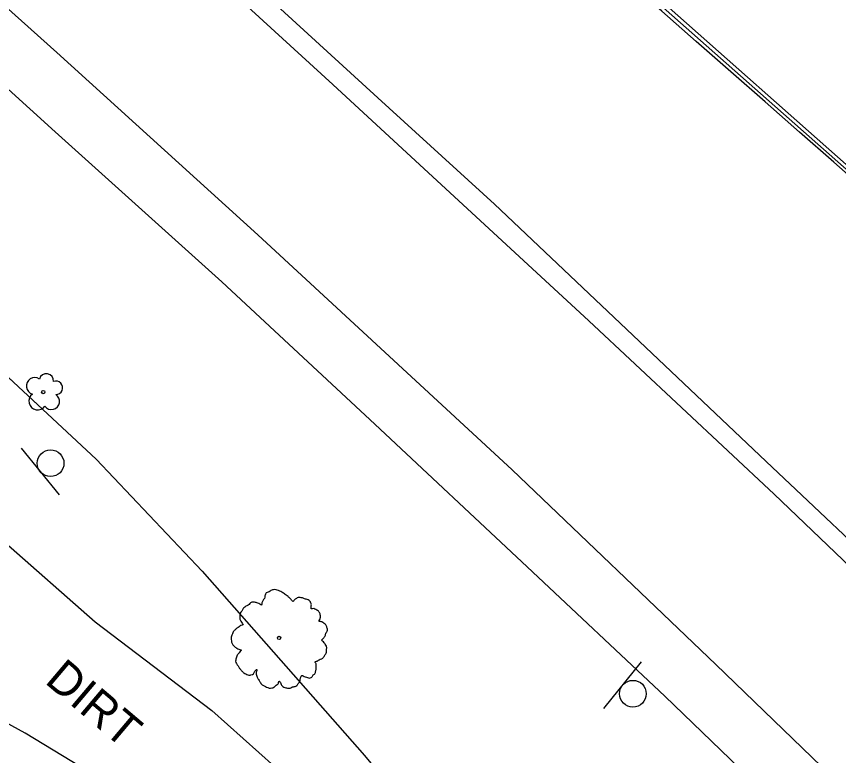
# Model space of a CAD drawing. Extents: x 2076109 to 2080761, y 592812 to 596750.
# Drawn here: x 2077395.6 to 2077518.8, y 595507.7 to 595618.3 of the extents above; entities that cross this region are included whole.
import ezdxf

# ---------------------------------------------------------------- set-up
doc = ezdxf.new("R2010")
doc.units = 0
for name, color, linetype in [('Default', 7, 'Continuous'), ('RD_EX_BldgApp', 7, 'Continuous'), ('RD_EX_Fence_ChLk', 7, 'Continuous'), ('RD_EX_Misc', 7, 'Continuous'), ('RD_EX_Road', 7, 'Continuous'), ('RD_EX_Road_txCode', 7, 'Continuous'), ('RD_EX_VEG', 7, 'Continuous'), ('RD_HC_Cl', 7, 'Continuous')]:
    doc.layers.add(name, color=color, linetype=linetype)

msp = doc.modelspace()

# ---------------------------------------------------------------- linework, layer by layer
at = {"layer": 'Default'}
for p, q in [((2077364.31, 595733.06), (2078453.96, 594769.07)), ((2077364.31, 595733.06), (2078453.96, 594769.07)), ((2077404.89, 595698.18), (2078420.27, 594797.03)), ((2077404.89, 595698.18), (2078420.27, 594797.03))]:
    msp.add_line(p, q, dxfattribs=at)
msp.add_arc((2035586.7, 547847.96), 63546.51, 48.5011873, 49.2923126, dxfattribs=at)
msp.add_arc((2035586.7, 547847.96), 63546.51, 48.5011873, 49.2923126, dxfattribs=at)
at = {"layer": 'RD_EX_BldgApp'}
for p, q in [((2077396.33, 595553.65), (2077402.01, 595546.67)), ((2077396.33, 595553.65), (2077402.01, 595546.67)), ((2077489.21, 595521.7), (2077483.57, 595514.69)), ((2077489.21, 595521.7), (2077483.57, 595514.69))]:
    msp.add_line(p, q, dxfattribs=at)
for centre in [(2077400.75, 595551.42), (2077400.75, 595551.42), (2077487.96, 595516.91), (2077487.96, 595516.91)]:
    msp.add_circle(centre, 2, dxfattribs=at)
at = {"layer": 'RD_EX_Fence_ChLk'}
msp.add_lwpolyline([(2077335.75, 595618.26), (2077356.53, 595599.53), (2077407.57, 595552.05), (2077423.46, 595535.25), (2077447.78, 595507.68), (2077494.27, 595451.57), (2077527.1, 595411.56), (2077548.1, 595385.61), (2077582.49, 595344.46)], dxfattribs=at)
msp.add_lwpolyline([(2077335.75, 595618.26), (2077356.53, 595599.53), (2077407.57, 595552.05), (2077423.46, 595535.25), (2077447.78, 595507.68), (2077494.27, 595451.57), (2077527.1, 595411.56), (2077548.1, 595385.61), (2077582.49, 595344.46)], dxfattribs=at)
at = {"layer": 'RD_EX_Misc'}
for points in [[(2077850.7, 595201.63), (2077820.53, 595232.8), (2077790.22, 595263.88), (2077762.8, 595291.76), (2077736.42, 595318.96), (2077709.92, 595346.36), (2077678.72, 595378.46), (2077649.91, 595408.22), (2077612.46, 595446.3), (2077577.19, 595481.07), (2077550.3, 595507.41), (2077509.12, 595546.77), (2077481.37, 595572.73), (2077443, 595608.1), (2077400.67, 595646.86), (2077373.88, 595670.82), (2077334.03, 595706.37), (2077304.56, 595732)], [(2077850.7, 595201.63), (2077820.53, 595232.8), (2077790.22, 595263.88), (2077762.8, 595291.76), (2077736.42, 595318.96), (2077709.92, 595346.36), (2077678.72, 595378.46), (2077649.91, 595408.22), (2077612.46, 595446.3), (2077577.19, 595481.07), (2077550.3, 595507.41), (2077509.12, 595546.77), (2077481.37, 595572.73), (2077443, 595608.1), (2077400.67, 595646.86), (2077373.88, 595670.82), (2077334.03, 595706.37), (2077304.56, 595732)], [(2077812.69, 595205.74), (2077779.15, 595240.73), (2077743.86, 595277.34), (2077707.16, 595314.93), (2077677.78, 595345.17), (2077641.95, 595381.51), (2077607.57, 595416.21), (2077570.67, 595452.82), (2077540.71, 595482.36), (2077500.4, 595521.29), (2077469.88, 595550.44), (2077431.8, 595585.6), (2077401.7, 595612.91), (2077373.73, 595637.96), (2077342.22, 595666.06), (2077323.28, 595683.05), (2077307.69, 595696.83), (2077294.47, 595708.58)], [(2077812.69, 595205.74), (2077779.15, 595240.73), (2077743.86, 595277.34), (2077707.16, 595314.93), (2077677.78, 595345.17), (2077641.95, 595381.51), (2077607.57, 595416.21), (2077570.67, 595452.82), (2077540.71, 595482.36), (2077500.4, 595521.29), (2077469.88, 595550.44), (2077431.8, 595585.6), (2077401.7, 595612.91), (2077373.73, 595637.96), (2077342.22, 595666.06), (2077323.28, 595683.05), (2077307.69, 595696.83), (2077294.47, 595708.58)]]:
    msp.add_lwpolyline(points, dxfattribs=at)
at = {"layer": 'RD_EX_Road'}
for points in [[(2077528.44, 595532.32), (2077507.93, 595551.7), (2077491.72, 595567.02), (2077467.24, 595590.18), (2077449.74, 595606.14), (2077431.68, 595622.71), (2077417.63, 595635.43), (2077400.96, 595650.59), (2077383.92, 595665.65), (2077365.24, 595682.19), (2077343.44, 595701.66), (2077326.52, 595716.21), (2077315.27, 595726.7), (2077317.91, 595731.12), (2077318.69, 595732.86), (2077319.09, 595734.63), (2077318.89, 595736.63), (2077318.61, 595737.93), (2077317.61, 595740.01), (2077315.19, 595742.84)], [(2077528.44, 595532.32), (2077507.93, 595551.7), (2077491.72, 595567.02), (2077467.24, 595590.18), (2077449.74, 595606.14), (2077431.68, 595622.71), (2077417.63, 595635.43), (2077400.96, 595650.59), (2077383.92, 595665.65), (2077365.24, 595682.19), (2077343.44, 595701.66), (2077326.52, 595716.21), (2077315.27, 595726.7), (2077317.91, 595731.12), (2077318.69, 595732.86), (2077319.09, 595734.63), (2077318.89, 595736.63), (2077318.61, 595737.93), (2077317.61, 595740.01), (2077315.19, 595742.84)], [(2077277.58, 595711.76), (2077294.44, 595696.44), (2077316.48, 595676.87), (2077339.86, 595656.39), (2077363.23, 595635.78), (2077381.85, 595618.74), (2077401.46, 595601.04), (2077426.38, 595578.58), (2077449.29, 595557.26), (2077472.1, 595535.89), (2077492.72, 595516.55), (2077515.1, 595494.99), (2077537.08, 595473.82), (2077562.41, 595448.47), (2077584.67, 595425.87), (2077605.91, 595404.49), (2077629.68, 595380.24), (2077656.48, 595352.83), (2077679.73, 595328.95), (2077700.7, 595307.57), (2077723.07, 595284.36), (2077743.1, 595263.78)], [(2077277.58, 595711.76), (2077294.44, 595696.44), (2077316.48, 595676.87), (2077339.86, 595656.39), (2077363.23, 595635.78), (2077381.85, 595618.74), (2077401.46, 595601.04), (2077426.38, 595578.58), (2077449.29, 595557.26), (2077472.1, 595535.89), (2077492.72, 595516.55), (2077515.1, 595494.99), (2077537.08, 595473.82), (2077562.41, 595448.47), (2077584.67, 595425.87), (2077605.91, 595404.49), (2077629.68, 595380.24), (2077656.48, 595352.83), (2077679.73, 595328.95), (2077700.7, 595307.57), (2077723.07, 595284.36), (2077743.1, 595263.78)], [(2077346.77, 595547.28), (2077355.73, 595550.52), (2077361.85, 595554.44), (2077363.05, 595555.59), (2077366.52, 595558.99), (2077367.63, 595559.7), (2077368.77, 595560.12), (2077371.79, 595560.32), (2077374.2, 595559.7), (2077376.79, 595557.92), (2077382.65, 595552.16), (2077393.59, 595539.87), (2077407.44, 595527.68), (2077424.88, 595514.4), (2077434.28, 595506.02), (2077440.79, 595499.75), (2077450.22, 595489.51), (2077459.53, 595479.21), (2077470.11, 595467.28), (2077482.62, 595451.09), (2077496.97, 595433.21), (2077510.29, 595416.4)], [(2077346.77, 595547.28), (2077355.73, 595550.52), (2077361.85, 595554.44), (2077363.05, 595555.59), (2077366.52, 595558.99), (2077367.63, 595559.7), (2077368.77, 595560.12), (2077371.79, 595560.32), (2077374.2, 595559.7), (2077376.79, 595557.92), (2077382.65, 595552.16), (2077393.59, 595539.87), (2077407.44, 595527.68), (2077424.88, 595514.4), (2077434.28, 595506.02), (2077440.79, 595499.75), (2077450.22, 595489.51), (2077459.53, 595479.21), (2077470.11, 595467.28), (2077482.62, 595451.09), (2077496.97, 595433.21), (2077510.29, 595416.4)], [(2077487.55, 595417.58), (2077476.5, 595431.92), (2077463.88, 595447.47), (2077449.41, 595464.91), (2077440.02, 595475.38), (2077428.51, 595487.52), (2077418.25, 595496.57), (2077410.91, 595502.5), (2077396.96, 595511), (2077388.9, 595515.38), (2077382.98, 595517.73), (2077375.2, 595520.32)], [(2077487.55, 595417.58), (2077476.5, 595431.92), (2077463.88, 595447.47), (2077449.41, 595464.91), (2077440.02, 595475.38), (2077428.51, 595487.52), (2077418.25, 595496.57), (2077410.91, 595502.5), (2077396.96, 595511), (2077388.9, 595515.38), (2077382.98, 595517.73), (2077375.2, 595520.32)]]:
    msp.add_lwpolyline(points, dxfattribs=at)
at = {"layer": 'RD_EX_VEG'}
for centre, radius in [((2077399.66, 595562.08), 0.25), ((2077399.66, 595562.08), 0.25), ((2077434.96, 595525.27), 0.25), ((2077434.96, 595525.27), 0.25), ((2077434.94, 595525.27), 0.0001), ((2077434.94, 595525.27), 0.0001)]:
    msp.add_circle(centre, radius, dxfattribs=at)
for centre, radius, start, end in [((2077400.11, 595563.73), 1.08, 354.7355, 164.5153), ((2077400.11, 595563.73), 1.08, 354.7355, 164.5153), ((2077398.37, 595562.98), 1.26, 56.211, 254.4932), ((2077398.37, 595562.98), 1.26, 56.211, 254.4932), ((2077401.56, 595562.71), 0.995, 268.5218, 111.806), ((2077401.56, 595562.71), 0.995, 268.5218, 111.806), ((2077398.82, 595560.71), 1.32, 126.6419, 325.5182), ((2077398.82, 595560.71), 1.32, 126.6419, 325.5182), ((2077400.88, 595560.68), 1.22, 216.3259, 57.8639), ((2077400.88, 595560.68), 1.22, 216.3259, 57.8639)]:
    msp.add_arc(centre, radius, start, end, dxfattribs=at)
for points in [[(2077439.7, 595530.66), (2077439.48, 595530.87), (2077439.17, 595531.01), (2077438.91, 595531.09), (2077438.69, 595531.18), (2077438.46, 595531.25), (2077438.12, 595531.31), (2077437.82, 595531.3), (2077437.56, 595531.19), (2077437.38, 595531.05), (2077437.16, 595530.87), (2077437.05, 595530.74), (2077436.94, 595530.8), (2077436.84, 595530.92), (2077436.69, 595531.14), (2077436.5, 595531.3), (2077436.31, 595531.46), (2077436.03, 595531.67), (2077435.76, 595531.89), (2077435.52, 595532.03), (2077435.24, 595532.2), (2077434.87, 595532.35), (2077434.53, 595532.48), (2077434.14, 595532.48), (2077433.64, 595532.28), (2077433.32, 595532.1), (2077433.04, 595532), (2077432.86, 595531.56), (2077432.77, 595531.18), (2077432.66, 595531.01), (2077432.44, 595530.64), (2077432.38, 595530.4), (2077432.34, 595530.17), (2077432.27, 595530.2), (2077431.95, 595530.4), (2077431.66, 595530.52), (2077431.19, 595530.62), (2077430.87, 595530.6), (2077430.58, 595530.41), (2077430.34, 595530.16), (2077430.13, 595530.08), (2077429.9, 595529.91), (2077429.83, 595529.87), (2077429.58, 595529.66), (2077429.37, 595529.25), (2077429.16, 595528.97), (2077429.11, 595528.71), (2077429.11, 595528.48), (2077429.09, 595528.18), (2077429.25, 595527.75), (2077429.43, 595527.46), (2077429.57, 595527.32), (2077429.11, 595527.05), (2077428.85, 595526.81), (2077428.49, 595526.59), (2077428.44, 595526.53), (2077428.1, 595526.2), (2077428, 595525.86), (2077427.82, 595525.52), (2077427.81, 595525.24), (2077427.82, 595524.83), (2077427.92, 595524.45), (2077428.23, 595524.03), (2077428.55, 595523.79), (2077429.1, 595523.55), (2077429.34, 595523.45), (2077429.21, 595523.33), (2077428.98, 595523.03), (2077428.71, 595522.7), (2077428.61, 595522.36), (2077428.51, 595522.09), (2077428.46, 595521.8), (2077428.57, 595521.42), (2077428.82, 595521.1), (2077429.05, 595520.71), (2077429.35, 595520.36), (2077429.71, 595520.02), (2077430.27, 595519.75), (2077430.56, 595519.67), (2077430.75, 595519.74), (2077431.14, 595519.89), (2077431.25, 595520.1), (2077431.65, 595520.54), (2077431.62, 595520.34), (2077431.53, 595519.96), (2077431.71, 595519.41), (2077431.91, 595519.02), (2077432.17, 595518.6), (2077432.35, 595518.34), (2077432.76, 595518.1), (2077433.1, 595517.91), (2077433.46, 595517.76), (2077433.87, 595517.78), (2077434.18, 595517.88), (2077434.4, 595518.05), (2077434.7, 595518.29), (2077434.85, 595518.39)], [(2077439.7, 595530.66), (2077439.48, 595530.87), (2077439.17, 595531.01), (2077438.91, 595531.09), (2077438.69, 595531.18), (2077438.46, 595531.25), (2077438.12, 595531.31), (2077437.82, 595531.3), (2077437.56, 595531.19), (2077437.38, 595531.05), (2077437.16, 595530.87), (2077437.05, 595530.74), (2077436.94, 595530.8), (2077436.84, 595530.92), (2077436.69, 595531.14), (2077436.5, 595531.3), (2077436.31, 595531.46), (2077436.03, 595531.67), (2077435.76, 595531.89), (2077435.52, 595532.03), (2077435.24, 595532.2), (2077434.87, 595532.35), (2077434.53, 595532.48), (2077434.14, 595532.48), (2077433.64, 595532.28), (2077433.32, 595532.1), (2077433.04, 595532), (2077432.86, 595531.56), (2077432.77, 595531.18), (2077432.66, 595531.01), (2077432.44, 595530.64), (2077432.38, 595530.4), (2077432.34, 595530.17), (2077432.27, 595530.2), (2077431.95, 595530.4), (2077431.66, 595530.52), (2077431.19, 595530.62), (2077430.87, 595530.6), (2077430.58, 595530.41), (2077430.34, 595530.16), (2077430.13, 595530.08), (2077429.9, 595529.91), (2077429.83, 595529.87), (2077429.58, 595529.66), (2077429.37, 595529.25), (2077429.16, 595528.97), (2077429.11, 595528.71), (2077429.11, 595528.48), (2077429.09, 595528.18), (2077429.25, 595527.75), (2077429.43, 595527.46), (2077429.57, 595527.32), (2077429.11, 595527.05), (2077428.85, 595526.81), (2077428.49, 595526.59), (2077428.44, 595526.53), (2077428.1, 595526.2), (2077428, 595525.86), (2077427.82, 595525.52), (2077427.81, 595525.24), (2077427.82, 595524.83), (2077427.92, 595524.45), (2077428.23, 595524.03), (2077428.55, 595523.79), (2077429.1, 595523.55), (2077429.34, 595523.45), (2077429.21, 595523.33), (2077428.98, 595523.03), (2077428.71, 595522.7), (2077428.61, 595522.36), (2077428.51, 595522.09), (2077428.46, 595521.8), (2077428.57, 595521.42), (2077428.82, 595521.1), (2077429.05, 595520.71), (2077429.35, 595520.36), (2077429.71, 595520.02), (2077430.27, 595519.75), (2077430.56, 595519.67), (2077430.75, 595519.74), (2077431.14, 595519.89), (2077431.25, 595520.1), (2077431.65, 595520.54), (2077431.62, 595520.34), (2077431.53, 595519.96), (2077431.71, 595519.41), (2077431.91, 595519.02), (2077432.17, 595518.6), (2077432.35, 595518.34), (2077432.76, 595518.1), (2077433.1, 595517.91), (2077433.46, 595517.76), (2077433.87, 595517.78), (2077434.18, 595517.88), (2077434.4, 595518.05), (2077434.7, 595518.29), (2077434.85, 595518.39)], [(2077434.85, 595518.39), (2077434.9, 595518.57), (2077435.03, 595518.8), (2077435.07, 595518.73), (2077435.17, 595518.58), (2077435.3, 595518.31), (2077435.42, 595518.1), (2077435.69, 595517.91), (2077435.96, 595517.81), (2077436.48, 595517.73), (2077437, 595517.92), (2077437.47, 595518.04), (2077437.73, 595518.24), (2077437.84, 595518.45), (2077438.14, 595518.84), (2077438.15, 595519.16), (2077438.19, 595519.29), (2077438.38, 595519.66), (2077438.47, 595519.65), (2077438.71, 595519.51), (2077439.08, 595519.37), (2077439.37, 595519.28), (2077439.65, 595519.27), (2077439.85, 595519.39), (2077440.09, 595519.72), (2077440.39, 595519.99), (2077440.43, 595520.15), (2077440.45, 595520.33), (2077440.52, 595520.53), (2077440.5, 595520.74), (2077440.52, 595520.92), (2077440.51, 595521.06), (2077440.51, 595521.26), (2077440.46, 595521.47), (2077440.38, 595521.6), (2077440.44, 595521.75), (2077440.68, 595521.8), (2077440.78, 595521.85), (2077440.95, 595522), (2077441.35, 595522.13), (2077441.64, 595522.4), (2077441.88, 595522.76), (2077442.02, 595523), (2077442.08, 595523.3), (2077442.09, 595523.62), (2077442.11, 595523.84), (2077442.05, 595524.05), (2077441.89, 595524.35), (2077441.73, 595524.55), (2077441.46, 595524.78), (2077441.34, 595524.94), (2077441.39, 595524.97), (2077441.49, 595525.08), (2077441.67, 595525.29), (2077441.9, 595525.68), (2077442.11, 595526.16), (2077442.13, 595526.18), (2077442.21, 595526.44), (2077442.17, 595526.73), (2077442.1, 595526.92), (2077442.03, 595527.15), (2077441.85, 595527.33), (2077441.62, 595527.52), (2077441.38, 595527.66), (2077441.16, 595527.71), (2077440.95, 595527.73), (2077440.99, 595527.89), (2077441.11, 595528.19), (2077441.17, 595528.33), (2077441.16, 595528.56), (2077441.12, 595528.86), (2077440.86, 595529.25), (2077440.33, 595529.59), (2077439.98, 595529.64), (2077439.75, 595529.6), (2077439.79, 595529.73), (2077439.77, 595530.01), (2077439.8, 595530.21), (2077439.75, 595530.42), (2077439.7, 595530.59), (2077439.66, 595530.69)], [(2077434.85, 595518.39), (2077434.9, 595518.57), (2077435.03, 595518.8), (2077435.07, 595518.73), (2077435.17, 595518.58), (2077435.3, 595518.31), (2077435.42, 595518.1), (2077435.69, 595517.91), (2077435.96, 595517.81), (2077436.48, 595517.73), (2077437, 595517.92), (2077437.47, 595518.04), (2077437.73, 595518.24), (2077437.84, 595518.45), (2077438.14, 595518.84), (2077438.15, 595519.16), (2077438.19, 595519.29), (2077438.38, 595519.66), (2077438.47, 595519.65), (2077438.71, 595519.51), (2077439.08, 595519.37), (2077439.37, 595519.28), (2077439.65, 595519.27), (2077439.85, 595519.39), (2077440.09, 595519.72), (2077440.39, 595519.99), (2077440.43, 595520.15), (2077440.45, 595520.33), (2077440.52, 595520.53), (2077440.5, 595520.74), (2077440.52, 595520.92), (2077440.51, 595521.06), (2077440.51, 595521.26), (2077440.46, 595521.47), (2077440.38, 595521.6), (2077440.44, 595521.75), (2077440.68, 595521.8), (2077440.78, 595521.85), (2077440.95, 595522), (2077441.35, 595522.13), (2077441.64, 595522.4), (2077441.88, 595522.76), (2077442.02, 595523), (2077442.08, 595523.3), (2077442.09, 595523.62), (2077442.11, 595523.84), (2077442.05, 595524.05), (2077441.89, 595524.35), (2077441.73, 595524.55), (2077441.46, 595524.78), (2077441.34, 595524.94), (2077441.39, 595524.97), (2077441.49, 595525.08), (2077441.67, 595525.29), (2077441.9, 595525.68), (2077442.11, 595526.16), (2077442.13, 595526.18), (2077442.21, 595526.44), (2077442.17, 595526.73), (2077442.1, 595526.92), (2077442.03, 595527.15), (2077441.85, 595527.33), (2077441.62, 595527.52), (2077441.38, 595527.66), (2077441.16, 595527.71), (2077440.95, 595527.73), (2077440.99, 595527.89), (2077441.11, 595528.19), (2077441.17, 595528.33), (2077441.16, 595528.56), (2077441.12, 595528.86), (2077440.86, 595529.25), (2077440.33, 595529.59), (2077439.98, 595529.64), (2077439.75, 595529.6), (2077439.79, 595529.73), (2077439.77, 595530.01), (2077439.8, 595530.21), (2077439.75, 595530.42), (2077439.7, 595530.59), (2077439.66, 595530.69)]]:
    msp.add_spline(points, degree=3, dxfattribs=at)
at = {"layer": 'RD_HC_Cl'}
msp.add_line((2077404.89, 595698.18), (2077928.38, 595233.58), dxfattribs=at)
msp.add_line((2077404.89, 595698.18), (2077928.38, 595233.58), dxfattribs=at)

# ---------------------------------------------------------------- texts
at = {"layer": 'RD_EX_Road_txCode'}
msp.add_text('DIRT', height=5, rotation=319.7592, dxfattribs=at).set_placement((2077399.72, 595518.62))
msp.add_text('DIRT', height=5, rotation=319.7592, dxfattribs=at).set_placement((2077399.72, 595518.62))

doc.saveas('drawing.dxf')
